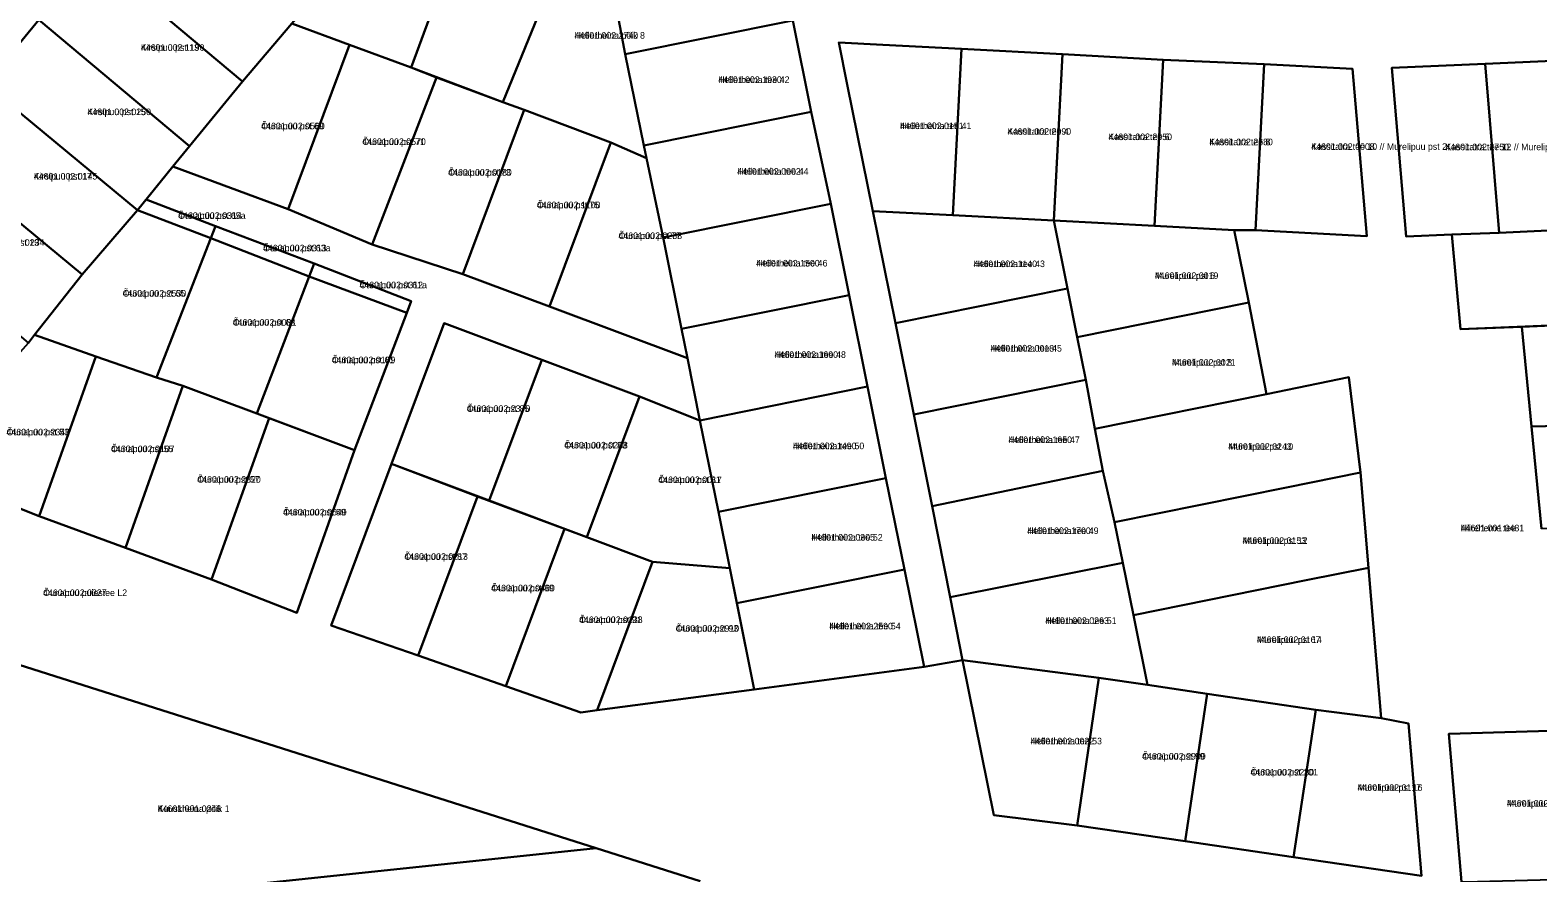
# Model space of a CAD drawing. Extents: x 551843 to 558501, y 6589003 to 6595718.
# Drawn here: x 552845.1 to 553189.3, y 6593188.1 to 6593380.5 of the extents above; entities that cross this region are included whole.
import ezdxf

# ---------------------------------------------------------------- set-up
doc = ezdxf.new("R2010")
doc.units = 0
for name, color, linetype in [('L_AADRESS', 7, 'Continuous'), ('PIIR', 7, 'Continuous'), ('TUNNUS', 7, 'Continuous')]:
    doc.layers.add(name, color=color, linetype=linetype)

msp = doc.modelspace()

# ---------------------------------------------------------------- linework, layer by layer
at = {"layer": 'PIIR'}
for points in [[(552844.73, 6593403.44), (552873.04, 6593438.03), (552878.63, 6593444.96), (552904.88, 6593476.66), (552929.12, 6593505.81), (552938.2, 6593516.55), (552964.95, 6593548.93), (552982.46, 6593567.41), (552985.76, 6593550.93), (552950.83, 6593508.47), (552926.78, 6593479.25), (552918.45, 6593469.47), (552903.02, 6593450.96), (552895.88, 6593441.74), (552883.68, 6593427), (552871.49, 6593412.26), (552859.3, 6593397.52), (552847.11, 6593382.78), (552834.92, 6593368.05)], [(553162.74, 6593187.4), (553159.76, 6593222.2), (553153.51, 6593223.4), (553150.61, 6593257.75), (553148.78, 6593279.48), (553146.19, 6593301.22), (553127.36, 6593297.4), (553123.35, 6593318.28), (553120.01, 6593334.83), (553124.85, 6593334.8), (553150.27, 6593333.43), (553146.99, 6593371.65), (553126.81, 6593372.71), (553103.78, 6593373.71), (553080.75, 6593374.94), (553057.72, 6593376.16), (553039.74, 6593377.11), (553029.68, 6593377.65), (553031.61, 6593368.03), (553037.48, 6593339.17), (553042.62, 6593313.57), (553046.82, 6593292.7), (553051.01, 6593271.83), (553055.17, 6593250.99), (553057.93, 6593236.65), (553049.17, 6593235.09), (553044.68, 6593257.37), (553040.45, 6593278.22), (553036.25, 6593299.08), (553032.06, 6593319.93), (553027.86, 6593340.79), (553023.39, 6593361.82), (553019.2, 6593382.68)], [(553199.54, 6593373.78), (553177.25, 6593372.78), (553155.97, 6593371.82), (553159.27, 6593333.32), (553169.66, 6593333.8), (553171.67, 6593312.2), (553185.68, 6593312.77), (553187.87, 6593289.99), (553190.11, 6593266.63)], [(552819.32, 6593280.52), (552847.12, 6593269.52), (552866.84, 6593262.31), (552886.52, 6593255.06), (552905.94, 6593247.45), (552919.16, 6593284.59), (552931.07, 6593315.91), (552932.09, 6593318.63), (552909.91, 6593327.17), (552887.39, 6593335.69), (552871.6, 6593341.81), (552877.67, 6593349.36), (552904, 6593339.6), (552923.18, 6593331.55), (552943.88, 6593324.78), (552963.68, 6593317.37), (552995.16, 6593305.59), (552998.02, 6593291.38), (552984.22, 6593296.83), (552961.94, 6593305.21), (552939.64, 6593313.55), (552927.6, 6593281.44), (552913.81, 6593244.59), (552933.64, 6593237.68), (552953.67, 6593230.7), (552970.81, 6593224.73), (552974.52, 6593225.23), (553010.42, 6593229.97), (553049.17, 6593235.09), (553057.93, 6593236.65), (553065.12, 6593201.25), (553084.12, 6593198.92), (553108.82, 6593195.31), (553133.54, 6593191.68), (553162.74, 6593187.4)], [(552798.93, 6593180.69), (552809.88, 6593199.24), (552819.89, 6593217.73), (552831.56, 6593239.02), (552840.87, 6593236.09), (552807.46, 6593176.14), (552974.33, 6593193.77), (552998.09, 6593186.23)], [(552998.09, 6593186.23), (552974.33, 6593193.77), (552840.87, 6593236.09)], [(553194.54, 6593220.58), (553168.98, 6593219.85), (553171.88, 6593186.05)]]:
    msp.add_lwpolyline(points, dxfattribs=at)
for points in [[(552871.49, 6593412.26), (552906.18, 6593383.58), (552904.84, 6593381.96), (552893.56, 6593368.77), (552859.3, 6593397.52)], [(552945.16, 6593407.45), (552932.04, 6593371.94), (552918, 6593377.08), (552904.84, 6593381.96), (552906.18, 6593383.58), (552918.37, 6593398.32), (552930.56, 6593413.06)], [(552945.16, 6593407.45), (552967.61, 6593399.86), (552953, 6593364), (552932.04, 6593371.94)], [(553019.2, 6593382.68), (552980.97, 6593374.99), (552977.03, 6593395.68), (553015.27, 6593403.37)], [(552980.97, 6593374.99), (552985.16, 6593354.13), (552985.77, 6593351.27), (552977.7, 6593354.83), (552957.91, 6593362.24), (552953, 6593364), (552967.61, 6593399.86), (552977.03, 6593395.68)], [(552859.3, 6593397.52), (552893.56, 6593368.77), (552881.45, 6593353.97), (552847.11, 6593382.78)], [(552881.45, 6593353.97), (552877.67, 6593349.36), (552869.6, 6593339.34), (552834.92, 6593368.05), (552847.11, 6593382.78)], [(552918, 6593377.08), (552904, 6593339.6), (552877.67, 6593349.36), (552881.45, 6593353.97), (552893.56, 6593368.77), (552904.84, 6593381.96)], [(553019.2, 6593382.68), (553023.39, 6593361.82), (552985.16, 6593354.13), (552980.97, 6593374.99)], [(552932.04, 6593371.94), (552937.85, 6593369.61), (552923.18, 6593331.55), (552904, 6593339.6), (552918, 6593377.08)], [(553031.61, 6593368.03), (553029.68, 6593377.65), (553039.74, 6593377.11), (553057.72, 6593376.16), (553055.76, 6593338.21), (553037.48, 6593339.17)], [(553080.75, 6593374.94), (553078.78, 6593337), (553055.76, 6593338.21), (553057.72, 6593376.16)], [(553103.78, 6593373.71), (553101.81, 6593335.79), (553078.78, 6593337), (553080.75, 6593374.94)], [(553103.78, 6593373.71), (553126.81, 6593372.71), (553124.85, 6593334.8), (553120.01, 6593334.83), (553101.81, 6593335.79)], [(553177.25, 6593372.78), (553199.54, 6593373.78), (553202.76, 6593335.25), (553199.56, 6593335.1), (553180.45, 6593334.21)], [(553146.99, 6593371.65), (553150.27, 6593333.43), (553124.85, 6593334.8), (553126.81, 6593372.71)], [(553177.25, 6593372.78), (553180.45, 6593334.21), (553169.66, 6593333.8), (553159.27, 6593333.32), (553155.97, 6593371.82)], [(552834.92, 6593368.05), (552869.6, 6593339.34), (552856.94, 6593324.66), (552822.25, 6593353.36)], [(552953, 6593364), (552957.91, 6593362.24), (552943.88, 6593324.78), (552923.18, 6593331.55), (552937.85, 6593369.61)], [(552943.88, 6593324.78), (552957.91, 6593362.24), (552977.7, 6593354.83), (552963.68, 6593317.37)], [(553027.86, 6593340.79), (552989.62, 6593333.1), (552985.77, 6593351.27), (552985.16, 6593354.13), (553023.39, 6593361.82)], [(552810.06, 6593338.62), (552822.25, 6593353.36), (552856.94, 6593324.66), (552846.1, 6593310.91), (552844.71, 6593309.11), (552828.37, 6593322.95)], [(552963.68, 6593317.37), (552977.7, 6593354.83), (552985.77, 6593351.27), (552989.62, 6593333.1), (552993.82, 6593312.24), (552995.16, 6593305.59)], [(552886.33, 6593332.95), (552873.91, 6593301.2), (552860.07, 6593305.95), (552846.1, 6593310.91), (552856.94, 6593324.66), (552869.6, 6593339.34)], [(552871.6, 6593341.81), (552887.39, 6593335.69), (552886.33, 6593332.95), (552869.6, 6593339.34)], [(553032.06, 6593319.93), (552993.82, 6593312.24), (552989.62, 6593333.1), (553027.86, 6593340.79)], [(553037.48, 6593339.17), (553055.76, 6593338.21), (553078.78, 6593337), (553081.9, 6593321.47), (553042.62, 6593313.57)], [(553101.81, 6593335.79), (553120.01, 6593334.83), (553123.35, 6593318.28), (553084.14, 6593310.34), (553081.9, 6593321.47), (553078.78, 6593337)], [(553169.66, 6593333.8), (553180.45, 6593334.21), (553202.76, 6593335.25), (553225.15, 6593336.34), (553235.34, 6593336.63), (553239.02, 6593314.75), (553202.98, 6593313.47), (553171.67, 6593312.2)], [(552908.79, 6593324.25), (552896.84, 6593292.94), (552879.98, 6593299.25), (552873.91, 6593301.2), (552886.33, 6593332.95)], [(552887.39, 6593335.69), (552909.91, 6593327.17), (552908.79, 6593324.25), (552886.33, 6593332.95)], [(552909.91, 6593327.17), (552932.09, 6593318.63), (552931.07, 6593315.91), (552908.79, 6593324.25)], [(552896.84, 6593292.94), (552908.79, 6593324.25), (552931.07, 6593315.91), (552919.16, 6593284.59)], [(553036.25, 6593299.08), (552998.02, 6593291.38), (552995.16, 6593305.59), (552993.82, 6593312.24), (553032.06, 6593319.93)], [(553081.9, 6593321.47), (553084.14, 6593310.34), (553086.1, 6593300.6), (553046.82, 6593292.7), (553042.62, 6593313.57)], [(553123.35, 6593318.28), (553127.36, 6593297.4), (553088.16, 6593289.44), (553086.1, 6593300.6), (553084.14, 6593310.34)], [(552961.94, 6593305.21), (552949.87, 6593273.1), (552927.6, 6593281.44), (552939.64, 6593313.55)], [(553187.87, 6593289.99), (553185.68, 6593312.77), (553202.98, 6593313.47), (553207.03, 6593290.47)], [(552819.32, 6593280.52), (552844.71, 6593309.11), (552846.1, 6593310.91), (552860.07, 6593305.95), (552847.12, 6593269.52)], [(552879.98, 6593299.25), (552866.84, 6593262.31), (552847.12, 6593269.52), (552860.07, 6593305.95), (552873.91, 6593301.2)], [(552961.94, 6593305.21), (552984.22, 6593296.83), (552972.15, 6593264.73), (552949.87, 6593273.1)], [(552886.52, 6593255.06), (552866.84, 6593262.31), (552879.98, 6593299.25), (552896.84, 6593292.94), (552899.64, 6593291.89)], [(553040.45, 6593278.22), (553002.22, 6593270.52), (552998.02, 6593291.38), (553036.25, 6593299.08)], [(553046.82, 6593292.7), (553086.1, 6593300.6), (553088.16, 6593289.44), (553090, 6593279.89), (553051.01, 6593271.83)], [(553088.16, 6593289.44), (553127.36, 6593297.4), (553146.19, 6593301.22), (553148.78, 6593279.48), (553131.92, 6593276.07), (553092.63, 6593268.11), (553090, 6593279.89)], [(553004.84, 6593257.62), (552987.17, 6593259.12), (552972.15, 6593264.73), (552984.22, 6593296.83), (552998.02, 6593291.38), (553002.22, 6593270.52)], [(552919.16, 6593284.59), (552905.94, 6593247.45), (552886.52, 6593255.06), (552899.64, 6593291.89)], [(553190.11, 6593266.63), (553187.87, 6593289.99), (553207.03, 6593290.47), (553211.2, 6593267.42)], [(552933.64, 6593237.68), (552913.81, 6593244.59), (552927.6, 6593281.44), (552947.24, 6593274.04)], [(553040.45, 6593278.22), (553044.68, 6593257.37), (553006.45, 6593249.66), (553004.84, 6593257.62), (553002.22, 6593270.52)], [(553051.01, 6593271.83), (553090, 6593279.89), (553092.63, 6593268.11), (553094.54, 6593258.84), (553055.17, 6593250.99)], [(553092.63, 6593268.11), (553131.92, 6593276.07), (553148.78, 6593279.48), (553150.61, 6593257.75), (553136.44, 6593254.88), (553096.96, 6593246.89), (553094.54, 6593258.84)], [(552947.24, 6593274.04), (552967.1, 6593266.62), (552953.67, 6593230.7), (552933.64, 6593237.68)], [(552970.81, 6593224.73), (552953.67, 6593230.7), (552967.1, 6593266.62), (552972.15, 6593264.73), (552987.17, 6593259.12), (552974.52, 6593225.23)], [(553004.84, 6593257.62), (553006.4, 6593249.71), (553010.42, 6593229.97), (552974.52, 6593225.23), (552987.17, 6593259.12)], [(553049.17, 6593235.09), (553010.42, 6593229.97), (553006.45, 6593249.66), (553044.68, 6593257.37)], [(553055.17, 6593250.99), (553094.54, 6593258.84), (553096.96, 6593246.89), (553100.16, 6593231), (553089.07, 6593232.59), (553057.93, 6593236.65)], [(553096.96, 6593246.89), (553136.44, 6593254.88), (553150.61, 6593257.75), (553153.51, 6593223.4), (553142.22, 6593224.87), (553138.6, 6593225.34), (553113.81, 6593228.95), (553100.16, 6593231)], [(552807.46, 6593176.14), (552840.87, 6593236.09), (552974.33, 6593193.77)], [(553089.07, 6593232.59), (553084.12, 6593198.92), (553065.12, 6593201.25), (553057.93, 6593236.65)], [(553100.16, 6593231), (553113.81, 6593228.95), (553108.82, 6593195.31), (553084.12, 6593198.92), (553089.07, 6593232.59)], [(553113.81, 6593228.95), (553138.6, 6593225.34), (553133.54, 6593191.68), (553108.82, 6593195.31)], [(553138.6, 6593225.34), (553142.22, 6593224.87), (553153.51, 6593223.4), (553159.76, 6593222.2), (553162.74, 6593187.4), (553133.54, 6593191.68)], [(553168.98, 6593219.85), (553194.54, 6593220.58), (553195.51, 6593186.59), (553172.63, 6593185.94), (553171.88, 6593186.05)]]:
    msp.add_lwpolyline(points, close=True, dxfattribs=at)

# ---------------------------------------------------------------- texts
at = {"layer": 'L_AADRESS'}
for s, p in [('Kirsipuu pst 13', (552870.37, 6593375.74)), ('Hellerheina põik 8', (552969.39, 6593378.51)), ('Hellerheina tee 42', (553002.18, 6593368.4)), ('Kirsipuu pst 15', (552858.18, 6593361.06)), ('Õunapuu pst 69', (552897.84, 6593357.83)), ('Hellerheina tee 41', (553043.7, 6593357.87)), ('Kassitatra tee 4', (553068.25, 6593356.58)), ('Kassitatra tee 6', (553091.28, 6593355.36)), ('Õunapuu pst 71', (552920.93, 6593354.25)), ('Kassitatra tee 8', (553114.31, 6593354.19)), ('Kassitatra tee 10 // Murelipuu pst 2', (553137.56, 6593353.13)), ('Kassitatra tee 12 // Murelipuu pst 1', (553168.21, 6593353.05)), ('Kirsipuu pst 17', (552845.92, 6593346.36)), ('Õunapuu pst 73', (552940.54, 6593347.24)), ('Hellerheina tee 44', (553006.51, 6593347.46)), ('Õunapuu pst 65a', (552878.88, 6593337.38)), ('Õunapuu pst 75', (552960.79, 6593339.81)), ('Kirsipuu pst 19', (552833.84, 6593331.24)), ('Õunapuu pst 77', (552979.42, 6593332.78)), ('Õunapuu pst 63a', (552898.27, 6593329.97)), ('Hellerheina tee 46', (553010.84, 6593326.51)), ('Hellerheina tee 43', (553060.48, 6593326.37)), ('Õunapuu pst 61a', (552920.28, 6593321.54)), ('Murelipuu pst 6', (553101.86, 6593323.67)), ('Õunapuu pst 65', (552866.21, 6593319.63)), ('Õunapuu pst 63', (552891.35, 6593313)), ('Hellerheina tee 45', (553064.36, 6593307.08)), ('Õunapuu pst 61', (552913.96, 6593304.43)), ('Hellerheina tee 48', (553015.04, 6593305.65)), ('Murelipuu pst 8', (553105.78, 6593303.86)), ('Õunapuu pst 85', (552944.77, 6593293.32)), ('Õunapuu pst 53', (552839.7, 6593287.96)), ('Hellerheina tee 47', (553068.45, 6593286.21)), ('Õunapuu pst 55', (552863.55, 6593284.13)), ('Õunapuu pst 83', (552967.04, 6593284.97)), ('Hellerheina tee 50', (553019.24, 6593284.8)), ('Murelipuu pst 10', (553118.62, 6593284.66)), ('Õunapuu pst 57', (552883.24, 6593277.15)), ('Õunapuu pst 81', (552988.5, 6593277.07)), ('Õunapuu pst 59', (552902.84, 6593269.68)), ('Hellerheina tee 49', (553072.73, 6593265.44)), ('Hiireherne tee', (553171.68, 6593266.06)), ('Hellerheina tee 52', (553023.45, 6593263.94)), ('Murelipuu pst 12', (553121.9, 6593263.19)), ('Õunapuu pst 87', (552930.53, 6593259.55)), ('Õunapuu puiestee L2', (552848.05, 6593251.29)), ('Õunapuu pst 89', (552950.37, 6593252.36)), ('Õunapuu pst 91', (552970.42, 6593245.12)), ('Hellerheina tee 51', (553076.85, 6593244.92)), ('Õunapuu pst 93', (552992.47, 6593243.14)), ('Hellerheina tee 54', (553027.55, 6593243.67)), ('Murelipuu pst 14', (553125.15, 6593240.57)), ('Hellerheina tee 53', (553073.5, 6593217.42)), ('Õunapuu pst 99', (553098.96, 6593213.96)), ('Õunapuu pst 101', (553123.71, 6593210.32)), ('Murelipuu pst 16', (553148.14, 6593206.82)), ('Kuuskheina põik 1', (552874.22, 6593202)), ('Murelipuu pst 17', (553182.24, 6593203.22))]:
    msp.add_text(s, height=1.5, dxfattribs=at).set_placement(p)
at = {"layer": 'TUNNUS'}
for s, p in [('44601:002:1190', (552870.37, 6593375.74)), ('44601:002:2740', (552969.39, 6593378.51)), ('44601:002:1930', (553002.18, 6593368.4)), ('44601:002:0250', (552858.18, 6593361.06)), ('44601:002:0560', (552897.84, 6593357.83)), ('44601:002:0151', (553043.7, 6593357.87)), ('44601:002:2090', (553068.25, 6593356.58)), ('44601:002:2050', (553091.28, 6593355.36)), ('44601:002:0570', (552920.93, 6593354.25)), ('44601:002:2680', (553114.31, 6593354.19)), ('44601:002:0008', (553137.56, 6593353.13)), ('44601:002:2750', (553168.21, 6593353.05)), ('44601:002:0145', (552845.92, 6593346.36)), ('44601:002:0180', (552940.54, 6593347.24)), ('44601:002:0002', (553006.51, 6593347.46)), ('44601:002:1100', (552960.79, 6593339.81)), ('44601:002:0314', (552878.88, 6593337.38)), ('44601:002:0234', (552833.84, 6593331.24)), ('44601:002:0238', (552979.42, 6593332.78)), ('44601:002:0313', (552898.27, 6593329.97)), ('44601:002:1500', (553010.84, 6593326.51)), ('44601:002:1140', (553060.48, 6593326.37)), ('44601:002:0312', (552920.28, 6593321.54)), ('44601:002:0019', (553101.86, 6593323.67)), ('44601:002:2530', (552866.21, 6593319.63)), ('44601:002:0081', (552891.35, 6593313)), ('44601:002:0018', (553064.36, 6593307.08)), ('44601:002:0109', (552913.96, 6593304.43)), ('44601:002:1690', (553015.04, 6593305.65)), ('44601:002:0021', (553105.78, 6593303.86)), ('44601:002:2370', (552944.77, 6593293.32)), ('44601:002:2340', (552839.7, 6593287.96)), ('44601:002:1650', (553068.45, 6593286.21)), ('44601:002:0107', (552863.55, 6593284.13)), ('44601:002:0208', (552967.04, 6593284.97)), ('44601:002:1490', (553019.24, 6593284.8)), ('44601:002:0243', (553118.62, 6593284.66)), ('44601:002:2320', (552883.24, 6593277.15)), ('44601:002:0017', (552988.5, 6593277.07)), ('44601:002:0640', (552902.84, 6593269.68)), ('44601:002:1700', (553072.73, 6593265.44)), ('44601:001:0481', (553171.68, 6593266.06)), ('44601:002:0305', (553023.45, 6593263.94)), ('44601:002:0153', (553121.9, 6593263.19)), ('44601:002:0213', (552930.53, 6593259.55)), ('44601:002:0460', (552950.37, 6593252.36)), ('44601:002:0327', (552848.05, 6593251.29)), ('44601:002:0138', (552970.42, 6593245.12)), ('44601:002:0263', (553076.85, 6593244.92)), ('44601:002:2910', (552992.47, 6593243.14)), ('44601:002:2590', (553027.55, 6593243.67)), ('44601:002:0167', (553125.15, 6593240.57)), ('44601:002:0022', (553073.5, 6593217.42)), ('44601:002:2900', (553098.96, 6593213.96)), ('44601:002:2280', (553123.71, 6593210.32)), ('44601:002:0117', (553148.14, 6593206.82)), ('44601:001:0246', (552874.22, 6593202)), ('44601:002:0152', (553182.24, 6593203.22))]:
    msp.add_text(s, height=1.5, dxfattribs=at).set_placement(p)

doc.saveas('drawing.dxf')
